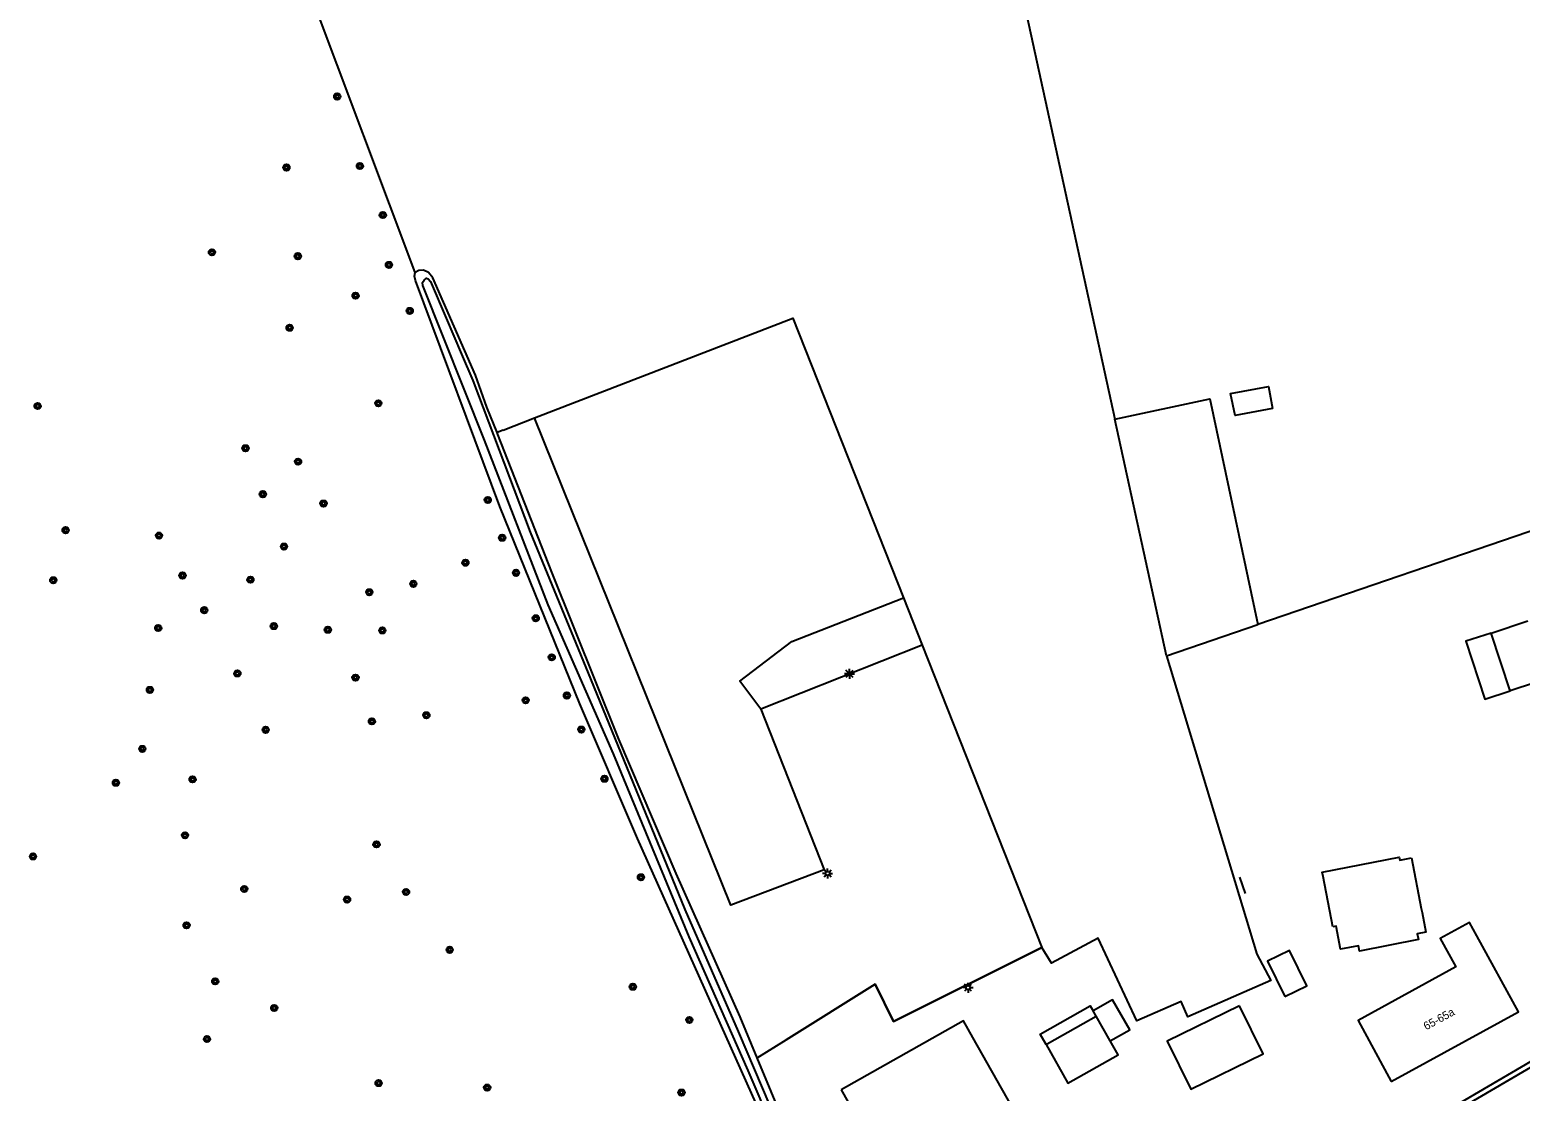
# Model space of a CAD drawing. Extents: x 140000 to 143000, y 403500 to 406000.
# Drawn here: x 141260.8 to 141447, y 405078.1 to 405210.7 of the extents above; entities that cross this region are included whole.
import ezdxf

# ---------------------------------------------------------------- set-up
doc = ezdxf.new("R2010")
doc.units = 0
for name, color, linetype in [('gg-afsc-erfafscheiding', 7, 'Continuous'), ('gg-afsc-hekwerk', 7, 'Continuous'), ('gg-anno-huisnummerreeks BGT', 7, 'Continuous'), ('gg-bbg-bijgebouw', 7, 'Continuous'), ('gg-bbg-gedigitaliseerde bijgebouw', 7, 'Continuous'), ('gg-bbg-hoofdgebouw', 7, 'Continuous'), ('gg-bbg-luifel en loopbrug', 7, 'Continuous'), ('gg-knt-bronhoudergrens', 7, 'Continuous'), ('gg-knt-onverhard', 7, 'Continuous'), ('gg-knt-verharding', 7, 'Continuous'), ('gg-kntw-bovenkant insteek waterloop', 7, 'Continuous'), ('gt-grn-groengrens', 7, 'Continuous'), ('gt-symb-boom', 7, 'Continuous'), ('gt-symb-lichtmast', 7, 'Continuous'), ('gx-grn-maaiveld', 7, 'Continuous')]:
    doc.layers.add(name, color=color, linetype=linetype)

# ---------------------------------------------------------------- blocks, each defined once
blk = doc.blocks.new('gt0-BOOM')
at = {"layer": 'gt-symb-boom'}
for radius in [0.4, 0.2]:
    blk.add_circle((0, 0), radius, dxfattribs=at)
blk = doc.blocks.new('gt0-LMAST')
at = {"layer": 'gt-symb-lichtmast'}
for p, q in [((-0.18, 0.17), (-0.45, 0.44)), ((-0.01, 0.25), (-0.01, 0.62)), ((0.17, 0.17), (0.44, 0.44)), ((-0.26, 0), (-0.63, 0)), ((-0.18, -0.18), (-0.45, -0.45)), ((-0.01, -0.25), (-0.01, -0.63)), ((0.44, -0.45), (0.17, -0.18)), ((0.24, 0), (0.62, 0))]:
    blk.add_line(p, q, dxfattribs=at)
blk.add_circle((-0.01, 0), 0.25, dxfattribs=at)

msp = doc.modelspace()

# ---------------------------------------------------------------- linework, layer by layer
at = {"layer": 'gg-afsc-erfafscheiding'}
msp.add_line((141359.81, 405062.7), (141351.69, 405082.21), dxfattribs=at)
for points in [[(141368.05, 405038.53), (141367.87, 405038.83), (141357.81, 405062.32), (141352.91, 405073.42), (141336.71, 405109.61), (141329.5, 405126.45), (141319.52, 405151.12), (141309.01, 405179.37), (141308.88, 405179.91), (141308.96, 405180.37)], [(141351.69, 405082.21), (141355.31, 405084.49), (141366.4, 405091.43), (141368.7, 405086.75), (141387.24, 405096)]]:
    msp.add_lwpolyline(points, dxfattribs=at)
at = {"layer": 'gg-afsc-hekwerk'}
msp.add_line((141411.91, 405104.8), (141412.65, 405102.75), dxfattribs=at)
msp.add_lwpolyline([(141387.24, 405096), (141368.7, 405086.75), (141366.4, 405091.43), (141355.31, 405084.49)], dxfattribs=at)
at = {"layer": 'gg-bbg-bijgebouw'}
msp.add_line((141395.78, 405084.33), (141394.02, 405087.44), dxfattribs=at)
for points in [[(141387.77, 405083.88), (141387.9, 405083.98), (141392.4, 405086.53), (141394.02, 405087.44)], [(141411.91, 405088.74), (141402.9, 405084.32), (141405.86, 405078.31), (141414.87, 405082.73), (141411.91, 405088.74)], [(141362.18, 405078.23), (141369.43, 405065.43), (141384.68, 405074), (141378.63, 405084.77), (141377.45, 405086.86), (141362.18, 405078.23)], [(141387.77, 405083.88), (141390.5, 405079.06), (141396.76, 405082.61), (141395.78, 405084.33)]]:
    msp.add_lwpolyline(points, dxfattribs=at)
at = {"layer": 'gg-bbg-gedigitaliseerde bijgebouw'}
for p, q in [((141433.41, 405107.22), (141434.63, 405100.89)), ((141423.57, 405098.58), (141422.36, 405104.89))]:
    msp.add_line(p, q, dxfattribs=at)
for points in [[(141422.36, 405104.89), (141422.25, 405105.44), (141431.88, 405107.3), (141431.95, 405106.94), (141433.41, 405107.22)], [(141434.63, 405100.89), (141434.73, 405100.39), (141435.2, 405097.93), (141434.14, 405097.73), (141434.29, 405096.99), (141426.92, 405095.57), (141426.8, 405096.22), (141424.56, 405095.78), (141424.01, 405098.66), (141423.57, 405098.58)]]:
    msp.add_lwpolyline(points, dxfattribs=at)
at = {"layer": 'gg-bbg-hoofdgebouw'}
for p, q in [((141443.35, 405135.3), (141447.93, 405136.82)), ((141445.73, 405128.08), (141443.35, 405135.3))]:
    msp.add_line(p, q, dxfattribs=at)
for points in [[(141451.57, 405138.01), (141458.93, 405140.45), (141461.31, 405133.2), (141445.73, 405128.08)], [(141430.89, 405079.27), (141446.79, 405087.98), (141441.59, 405097.48), (141440.67, 405099.14), (141437, 405097.13), (141438.95, 405093.58), (141426.73, 405086.88), (141430.89, 405079.27)]]:
    msp.add_lwpolyline(points, dxfattribs=at)
at = {"layer": 'gg-bbg-luifel en loopbrug'}
msp.add_line((141394.02, 405087.44), (141393.65, 405088.09), dxfattribs=at)
for points in [[(141443.35, 405135.3), (141440.22, 405134.27), (141442.59, 405127.04), (141445.73, 405128.08)], [(141417.6, 405089.88), (141420.35, 405091.22), (141418.18, 405095.65), (141415.43, 405094.31), (141417.6, 405089.88)], [(141395.78, 405084.33), (141398.21, 405085.71), (141396.08, 405089.46), (141393.65, 405088.09)], [(141387.77, 405083.88), (141387.02, 405085.19), (141393.29, 405088.74), (141393.65, 405088.09)]]:
    msp.add_lwpolyline(points, dxfattribs=at)
at = {"layer": 'gg-knt-bronhoudergrens'}
for p, q in [((141319.94, 405160.67), (141323.84, 405162.18)), ((141479.46, 405158.68), (141414.2, 405136.36)), ((141369.95, 405139.72), (141372.29, 405133.8)), ((141372.29, 405133.8), (141387.24, 405096))]:
    msp.add_line(p, q, dxfattribs=at)
for points in [[(141323.84, 405162.18), (141356.12, 405174.67), (141369.95, 405139.72)], [(141416.05, 405163.38), (141411.39, 405162.49), (141410.82, 405165.23), (141415.55, 405166.12), (141416.05, 405163.38)], [(141352.15, 405125.8), (141360.04, 405105.7), (141348.37, 405101.28), (141323.84, 405162.18)], [(141402.82, 405132.47), (141414.11, 405095.18), (141415.85, 405091.89), (141405.48, 405087.36), (141404.64, 405089.28), (141399.08, 405086.85), (141394.28, 405097.16), (141388.46, 405094.05), (141387.24, 405096)]]:
    msp.add_lwpolyline(points, dxfattribs=at)
at = {"layer": 'gg-knt-onverhard'}
for q in [(141396.36, 405162.04), (141414.2, 405136.36)]:
    msp.add_line((141402.82, 405132.47), q, dxfattribs=at)
msp.add_lwpolyline([(141396.36, 405162.04), (141408.22, 405164.56), (141414.2, 405136.36)], dxfattribs=at)
at = {"layer": 'gg-knt-verharding'}
msp.add_line((141451.74, 405083.76), (141433.47, 405073.09), dxfattribs=at)
for points in [[(141319.18, 405160.37), (141317.9, 405163.52), (141316.48, 405167.51), (141311.14, 405179.71), (141310.63, 405180.34), (141309.98, 405180.65), (141309.42, 405180.62), (141308.96, 405180.37)], [(141351.69, 405082.21), (141349.55, 405087.34), (141341.55, 405105.26), (141334.4, 405122.04), (141326.03, 405142.9), (141319.28, 405160.12), (141319.18, 405160.37)], [(141461.62, 405088.67), (141453.88, 405084.32), (141427.19, 405068.7), (141409.9, 405058.61), (141390.62, 405047.29), (141371.38, 405036.17)]]:
    msp.add_lwpolyline(points, dxfattribs=at)
at = {"layer": 'gg-kntw-bovenkant insteek waterloop'}
msp.add_lwpolyline([(141368.65, 405038.27), (141350.54, 405080.64), (141343.16, 405097.35), (141333.73, 405120.22), (141325.55, 405138.81), (141317.62, 405159.41), (141309.92, 405178.73), (141309.88, 405179.11), (141310.08, 405179.4), (141310.35, 405179.63), (141310.56, 405179.55), (141310.88, 405179.24), (141312.84, 405174.67), (141314.73, 405170.14), (141316.16, 405166.88), (141323.32, 405147.93), (141330.87, 405129.59), (141342.64, 405100.74), (141349.3, 405085.53), (141355.15, 405071.74)], dxfattribs=at)
at = {"layer": 'gt-grn-groengrens'}
for p, q in [((141370.79, 405279.08), (141396.36, 405162.04)), ((141308.96, 405180.37), (141285.64, 405242.45)), ((141372.29, 405133.8), (141352.15, 405125.8))]:
    msp.add_line(p, q, dxfattribs=at)
msp.add_lwpolyline([(141352.15, 405125.8), (141349.51, 405129.27), (141355.99, 405134.26), (141369.95, 405139.72)], dxfattribs=at)
at = {"layer": 'gx-grn-maaiveld'}
msp.add_line((141319.94, 405160.67), (141319.18, 405160.37), dxfattribs=at)

# ---------------------------------------------------------------- block references
at = {"layer": 'gt-symb-boom'}
for p in [(141299.21, 405202.35), (141292.87, 405193.48), (141302.04, 405193.66), (141304.91, 405187.54), (141283.56, 405182.88), (141294.29, 405182.4), (141305.67, 405181.31), (141301.5, 405177.46), (141308.27, 405175.56), (141293.26, 405173.45), (141261.78, 405163.67), (141304.35, 405164.01), (141287.75, 405158.4), (141294.32, 405156.72), (141289.92, 405152.66), (141297.5, 405151.48), (141318.02, 405151.93), (141265.28, 405148.16), (141276.95, 405147.48), (141319.82, 405147.21), (141292.56, 405146.11), (141315.23, 405144.09), (141321.55, 405142.83), (141263.74, 405141.9), (141279.88, 405142.49), (141288.37, 405141.97), (141308.72, 405141.45), (141303.22, 405140.4), (141282.6, 405138.16), (141276.85, 405135.93), (141291.29, 405136.17), (141298.04, 405135.71), (141304.85, 405135.63), (141324.01, 405137.15), (141326.01, 405132.27), (141286.74, 405130.26), (141275.81, 405128.2), (141301.49, 405129.73), (141322.75, 405126.9), (141327.9, 405127.5), (141303.54, 405124.27), (141310.35, 405125.03), (141290.27, 405123.21), (141329.71, 405123.24), (141274.86, 405120.83), (141281.14, 405117.02), (141332.59, 405117.09), (141271.56, 405116.59), (141280.2, 405110.03), (141304.12, 405108.9), (141261.21, 405107.39), (141337.15, 405104.79), (141287.6, 405103.32), (141300.44, 405102), (141307.81, 405102.95), (141280.39, 405098.78), (141313.26, 405095.72), (141283.97, 405091.78), (141336.14, 405091.1), (141291.34, 405088.45), (141343.2, 405086.95), (141282.94, 405084.57), (141304.38, 405079.06), (141317.94, 405078.5), (141342.22, 405077.88)]:
    msp.add_blockref('gt0-BOOM', p, dxfattribs=at)
at = {"layer": 'gt-symb-lichtmast'}
for p in [(141363.21, 405130.21), (141360.48, 405105.26), (141378.02, 405090.99)]:
    msp.add_blockref('gt0-LMAST', p, dxfattribs=at)

# ---------------------------------------------------------------- texts
at = {"layer": 'gg-anno-huisnummerreeks BGT'}
msp.add_text('65-65a', height=1, rotation=28.7, dxfattribs=at).set_placement((141435.25, 405085.65))

doc.saveas('drawing.dxf')
